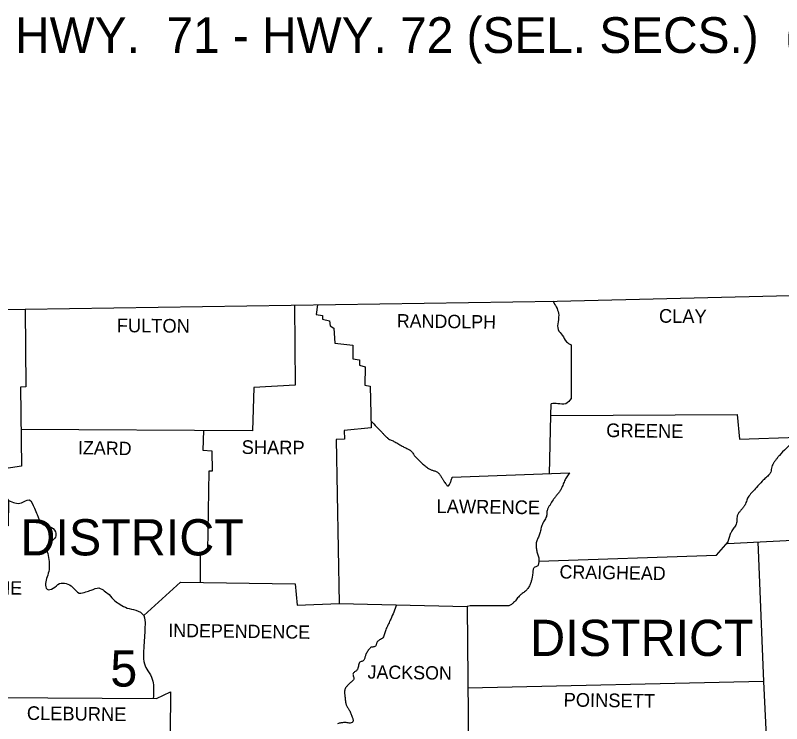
# Model space of a CAD drawing. Extents: x 6028647 to 6035072, y 5366486 to 5368495.
# Drawn here: x 6031371.9 to 6031613, y 5368223.1 to 5368446 of the extents above; entities that cross this region are included whole.
import ezdxf

# ---------------------------------------------------------------- set-up
doc = ezdxf.new("R2010")
doc.units = 0
doc.layers.add('Default', color=7, linetype='Continuous')
doc.layers.add('R_Border', color=7, linetype='Continuous')

msp = doc.modelspace()

# ---------------------------------------------------------------- linework, layer by layer
at = {"layer": 'Default'}
for p, q in [((6031540.38, 5368320.07), (6031540.46, 5368323.77)), ((6031595.96, 5368279.77), (6031597.04, 5368283.09))]:
    msp.add_line(p, q, dxfattribs=at)
for points in [[(6031071.37, 5368353.27), (6031233.07, 5368353.17), (6031374.96, 5368353.47), (6031542.36, 5368356.07), (6031619.96, 5368357.87)], [(6031459.66, 5368354.79), (6031459.86, 5368329.57), (6031446.86, 5368328.87), (6031446.46, 5368315.27), (6031373.63, 5368315.67)], [(6031466.94, 5368354.9), (6031466.56, 5368351.87), (6031468.56, 5368351.57), (6031468.46, 5368350.37), (6031470.76, 5368349.87), (6031470.96, 5368348.27), (6031472.06, 5368347.57), (6031472.36, 5368342.77), (6031478.06, 5368342.17), (6031478.06, 5368337.87), (6031480.16, 5368337.57), (6031480.16, 5368335.87), (6031481.96, 5368335.37), (6031481.86, 5368329.57), (6031483.46, 5368329.27), (6031483.86, 5368316.17), (6031475.36, 5368315.37), (6031475.46, 5368312.57), (6031472.86, 5368312.47), (6031473.76, 5368260.87), (6031514.06, 5368259.97), (6031514.76, 5368179.77), (6031488.46, 5368179.07), (6031487.94, 5368193.17)], [(6031374.96, 5368353.47), (6031375.16, 5368329.07), (6031373.46, 5368328.97), (6031373.76, 5368304.07), (6031366.76, 5368303.07), (6031367.36, 5368296.37), (6031369.76, 5368293.27), (6031369.56, 5368285.37), (6031355.97, 5368284.87), (6031355.46, 5368272.67), (6031343.07, 5368272.27), (6031342.47, 5368257.47), (6031343.16, 5368256.27), (6031343.47, 5368232.67), (6031364.86, 5368231.27), (6031364.56, 5368178.57), (6031381.56, 5368178.07), (6031381.56, 5368124.47), (6031368.16, 5368123.47), (6031367.16, 5368111.67), (6031344.67, 5368111.57)], [(6031546.76, 5368342.27), (6031546.76, 5368325.37)], [(6031539.94, 5368301.74), (6031540.38, 5368320.07), (6031540.46, 5368320.07), (6031598.96, 5368320.37), (6031599.76, 5368312.57), (6031618.12, 5368313.24)], [(6031431.08, 5368315.36), (6031430.86, 5368309.17), (6031433.66, 5368308.97), (6031433.76, 5368302.57), (6031432.76, 5368302.57), (6031432.36, 5368277.37), (6031430.06, 5368276.37), (6031430.06, 5368267.48)], [(6031509.36, 5368300.67), (6031546.23, 5368301.96)], [(6031595.96, 5368279.77), (6031671.86, 5368283.67)], [(6031536.62, 5368274.26), (6031592.46, 5368276.07), (6031596.14, 5368280.3)], [(6031605.54, 5368280.26), (6031607.26, 5368236.37), (6031609.3, 5368195.4)], [(6031412.26, 5368257.08), (6031423.86, 5368267.57), (6031459.86, 5368267.07), (6031460.56, 5368260.37), (6031473.76, 5368260.87)], [(6031527.16, 5368260.17), (6031514.96, 5368260.17), (6031514.06, 5368259.97)], [(6031607.26, 5368236.37), (6031514.29, 5368234.25)], [(6031364.86, 5368231.27), (6031416.26, 5368230.97), (6031420.66, 5368233.07), (6031420.36, 5368193.97), (6031417.36, 5368192.67), (6031414.66, 5368190.37), (6031413.76, 5368189.47), (6031413.66, 5368178.27), (6031374.76, 5368178.27)]]:
    msp.add_lwpolyline(points, dxfattribs=at)
for points in [[(6031619.96, 5368357.87), (6031620.05, 5368356.77), (6031620.17, 5368355.67), (6031620.3, 5368354.57), (6031620.46, 5368353.47), (6031620.7, 5368352.85), (6031621.1, 5368352.29), (6031621.54, 5368351.75), (6031621.86, 5368351.17), (6031621.99, 5368350.15), (6031621.87, 5368349.06), (6031621.79, 5368347.97), (6031621.86, 5368347.45), (6031622.06, 5368346.97), (6031622.82, 5368345.99), (6031623.76, 5368345.17), (6031624.48, 5368344.69), (6031625.22, 5368344.27), (6031625.96, 5368343.85), (6031626.66, 5368343.37), (6031628.11, 5368342.09), (6031628.72, 5368341.34), (6031629, 5368340.92), (6031629.26, 5368340.47), (6031629.63, 5368339.62), (6031629.84, 5368338.77), (6031629.91, 5368337.92), (6031629.86, 5368337.07), (6031629.69, 5368336.2), (6031629.44, 5368335.33), (6031629.21, 5368334.45), (6031629.06, 5368333.57), (6031629.01, 5368332.6), (6031628.98, 5368331.62), (6031628.94, 5368330.64), (6031628.86, 5368329.67), (6031628.46, 5368326.27), (6031628.28, 5368324.71), (6031628.12, 5368323.93), (6031628.01, 5368323.55), (6031627.86, 5368323.17), (6031626.82, 5368321.78), (6031625.46, 5368320.67), (6031624.89, 5368320.21), (6031624.31, 5368319.78), (6031623.73, 5368319.33), (6031623.16, 5368318.87), (6031621.06, 5368316.77), (6031620.67, 5368316.23), (6031620.33, 5368315.65), (6031619.99, 5368315.08), (6031619.56, 5368314.57), (6031616.96, 5368312.17), (6031614.36, 5368309.67), (6031612.26, 5368307.47), (6031611.69, 5368306.81), (6031611.16, 5368306.11), (6031610.65, 5368305.4), (6031610.16, 5368304.67), (6031609.86, 5368303.92), (6031609.71, 5368303.09), (6031609.54, 5368302.27), (6031609.39, 5368301.9), (6031609.16, 5368301.57), (6031608.61, 5368301), (6031608.02, 5368300.46), (6031607.43, 5368299.93), (6031606.86, 5368299.37), (6031605.06, 5368297.37), (6031602.66, 5368294.67), (6031602.27, 5368294.05), (6031602, 5368293.36), (6031601.76, 5368292.65), (6031601.46, 5368291.97), (6031600.93, 5368291.18), (6031600.3, 5368290.43), (6031599.68, 5368289.68), (6031599.16, 5368288.87), (6031598.95, 5368288.15), (6031598.89, 5368287.38), (6031598.84, 5368286.6), (6031598.66, 5368285.87), (6031598.34, 5368285.25), (6031597.94, 5368284.66), (6031597.53, 5368284.07), (6031597.16, 5368283.47), (6031597.04, 5368283.09)], [(6031540.95, 5368356.05), (6031542.76, 5368352.27), (6031542.66, 5368349.57), (6031542.66, 5368347.07), (6031543.96, 5368345.37), (6031545.26, 5368343.27), (6031546.76, 5368342.27)], [(6031546.76, 5368325.37), (6031545.06, 5368323.77), (6031542.56, 5368323.77), (6031540.46, 5368323.77)], [(6031483.8, 5368318.28), (6031485.47, 5368316.51), (6031487.16, 5368314.77), (6031487.4, 5368314.53), (6031488.09, 5368313.8), (6031488.56, 5368313.32), (6031488.81, 5368313.09), (6031488.94, 5368312.98), (6031489.06, 5368312.87), (6031489.58, 5368312.53), (6031490.14, 5368312.27), (6031490.71, 5368312.04), (6031491.26, 5368311.77), (6031492.57, 5368311.02), (6031493.86, 5368310.27), (6031494.44, 5368309.97), (6031495.03, 5368309.69), (6031495.89, 5368309.25), (6031496.03, 5368309.16), (6031496.16, 5368309.07), (6031496.61, 5368308.66), (6031496.96, 5368308.17), (6031497.29, 5368307.65), (6031497.47, 5368307.4), (6031497.66, 5368307.17), (6031498.7, 5368306.11), (6031499.76, 5368305.07), (6031500.27, 5368304.62), (6031500.79, 5368304.19), (6031501.33, 5368303.78), (6031501.86, 5368303.37), (6031502.68, 5368302.95), (6031503.59, 5368302.66), (6031504.46, 5368302.33), (6031504.84, 5368302.09), (6031505.01, 5368301.94), (6031505.16, 5368301.77), (6031505.46, 5368301.36), (6031505.73, 5368300.93), (6031505.99, 5368300.5), (6031506.26, 5368300.07), (6031506.45, 5368299.79), (6031506.64, 5368299.5), (6031507.02, 5368298.92), (6031507.39, 5368298.39), (6031507.58, 5368298.16), (6031507.67, 5368298.06), (6031507.72, 5368298.01), (6031507.76, 5368297.97), (6031507.88, 5368297.9), (6031507.99, 5368297.89), (6031508.21, 5368298.02), (6031508.65, 5368298.73), (6031509.04, 5368299.74), (6031509.21, 5368300.24), (6031509.36, 5368300.67)], [(6031546.23, 5368301.96), (6031545.39, 5368300.75), (6031544.66, 5368299.47), (6031544.35, 5368298.77), (6031544.09, 5368298.06), (6031543.81, 5368297.35), (6031543.46, 5368296.67), (6031542.9, 5368295.85), (6031542.29, 5368295.06), (6031541.66, 5368294.28), (6031541.06, 5368293.47), (6031540.1, 5368291.96), (6031539.66, 5368291.18), (6031539.26, 5368290.37), (6031539.13, 5368289.86), (6031539.1, 5368289.32), (6031539.07, 5368288.78), (6031538.96, 5368288.27), (6031538.64, 5368287.56), (6031538.25, 5368286.88), (6031537.87, 5368286.19), (6031537.56, 5368285.47), (6031537.35, 5368284.77), (6031537.16, 5368284.07), (6031536.97, 5368283.37), (6031536.76, 5368282.67), (6031536.55, 5368282.07), (6031536.31, 5368281.47), (6031536.07, 5368280.88), (6031535.86, 5368280.27), (6031535.75, 5368279.66), (6031535.74, 5368279.02), (6031535.79, 5368278.39), (6031535.86, 5368277.77), (6031536, 5368277.14), (6031536.2, 5368276.52), (6031536.41, 5368275.9), (6031536.56, 5368275.27), (6031536.63, 5368274.7), (6031536.61, 5368274.12), (6031536.52, 5368273.54), (6031536.45, 5368273.25), (6031536.36, 5368272.97), (6031536.06, 5368272.63), (6031535.6, 5368272.42), (6031535.14, 5368272.21), (6031534.86, 5368271.87), (6031534.79, 5368271.52), (6031534.73, 5368271.15), (6031534.66, 5368270.42), (6031534.59, 5368269.69), (6031534.46, 5368268.97), (6031534.2, 5368267.96), (6031533.86, 5368266.97), (6031533.31, 5368265.91), (6031532.96, 5368265.42), (6031532.56, 5368264.97), (6031532.11, 5368264.56), (6031531.62, 5368264.21), (6031531.12, 5368263.86), (6031530.66, 5368263.47), (6031530.15, 5368262.92), (6031529.68, 5368262.32), (6031529.19, 5368261.73), (6031528.66, 5368261.17), (6031527.96, 5368260.62), (6031527.58, 5368260.38), (6031527.16, 5368260.17)], [(6031369.76, 5368293.27), (6031373.76, 5368292.57), (6031376.16, 5368293.47), (6031377.86, 5368290.87), (6031378.76, 5368288.87), (6031380.26, 5368285.97), (6031382.66, 5368285.07), (6031384.46, 5368283.47), (6031384.46, 5368281.77), (6031382.86, 5368280.17), (6031381.66, 5368278.57), (6031382.06, 5368276.67), (6031382.46, 5368274.07), (6031382.46, 5368271.57), (6031381.86, 5368269.27), (6031381.36, 5368267.17), (6031381.86, 5368265.37), (6031383.76, 5368265.67), (6031385.76, 5368267.17), (6031387.86, 5368267.17), (6031389.86, 5368266.07), (6031391.96, 5368264.17), (6031394.06, 5368264.57), (6031395.76, 5368265.07), (6031398.16, 5368265.77), (6031399.86, 5368264.87), (6031401.36, 5368263.67), (6031403.16, 5368261.77), (6031404.86, 5368260.57), (6031407.06, 5368259.47), (6031409.76, 5368258.77), (6031412.26, 5368257.07), (6031412.66, 5368254.17), (6031412.56, 5368251.67), (6031412.36, 5368248.57), (6031412.16, 5368245.17), (6031412.46, 5368241.87), (6031413.56, 5368239.67), (6031414.96, 5368237.07), (6031415.36, 5368234.67), (6031415.26, 5368230.87)], [(6031491.83, 5368260.47), (6031490.94, 5368258.21), (6031489.96, 5368255.97), (6031489.62, 5368255.22), (6031489.27, 5368254.47), (6031488.91, 5368253.72), (6031488.56, 5368252.97), (6031488.32, 5368252.33), (6031488.12, 5368251.67), (6031487.91, 5368251.01), (6031487.66, 5368250.37), (6031487.29, 5368249.91), (6031486.77, 5368249.57), (6031486.22, 5368249.25), (6031485.97, 5368249.07), (6031485.76, 5368248.87), (6031485.59, 5368248.55), (6031485.48, 5368248.17), (6031485.36, 5368247.79), (6031485.16, 5368247.47), (6031484.79, 5368247.26), (6031484.31, 5368247.18), (6031483.84, 5368247.1), (6031483.46, 5368246.87), (6031483.27, 5368246.64), (6031483.09, 5368246.4), (6031482.75, 5368245.91), (6031482.44, 5368245.4), (6031482.16, 5368244.87), (6031481.99, 5368244.43), (6031481.87, 5368243.96), (6031481.75, 5368243.5), (6031481.56, 5368243.07), (6031481.28, 5368242.81), (6031480.88, 5368242.65), (6031480.47, 5368242.51), (6031480.16, 5368242.27), (6031480.03, 5368242.03), (6031479.93, 5368241.76), (6031479.8, 5368241.17), (6031479.67, 5368240.59), (6031479.53, 5368240.19), (6031479.46, 5368240.07), (6031479.18, 5368239.75), (6031478.81, 5368239.48), (6031478.44, 5368239.2), (6031478.16, 5368238.87), (6031478.11, 5368238.4), (6031478.26, 5368237.86), (6031478.38, 5368237.32), (6031478.26, 5368236.87), (6031478.18, 5368236.77), (6031478.1, 5368236.68), (6031477.52, 5368236.17), (6031477.13, 5368235.83), (6031476.76, 5368235.47), (6031476.42, 5368235.1), (6031476.09, 5368234.73), (6031475.79, 5368234.33), (6031475.66, 5368234.11), (6031475.56, 5368233.87), (6031475.44, 5368232.77), (6031475.56, 5368231.67), (6031475.64, 5368230.94), (6031475.72, 5368230.21), (6031475.85, 5368229.49), (6031475.95, 5368229.13), (6031476.06, 5368228.77), (6031476.28, 5368228.32), (6031476.54, 5368227.91), (6031476.82, 5368227.5), (6031477.06, 5368227.07), (6031477.55, 5368225.98), (6031477.77, 5368225.42), (6031477.96, 5368224.87), (6031478.08, 5368224.52), (6031478.14, 5368224.13), (6031478.09, 5368223.77), (6031478, 5368223.61), (6031477.94, 5368223.54), (6031477.86, 5368223.47), (6031477.25, 5368223.24), (6031476.62, 5368223.3), (6031475.99, 5368223.45), (6031475.67, 5368223.49), (6031475.36, 5368223.47), (6031474.84, 5368223.38), (6031474.31, 5368223.29), (6031473.79, 5368223.19), (6031473.26, 5368223.07)]]:
    msp.add_spline(points, degree=3, dxfattribs=at)

# ---------------------------------------------------------------- texts
for s, height, rotation, p in [('RANDOLPH', 4.201, 359.2583, (6031491.86, 5368347.77)), ('CLAY', 4.299, 359.2258, (6031574.36, 5368349.27)), ('FULTON', 4.3, 359.4996, (6031403.76, 5368346.27)), ('GREENE', 4.301, 359.2361, (6031557.76, 5368313.27)), ('IZARD', 4.199, 358.9258, (6031391.56, 5368307.87)), ('SHARP', 4.3, 359.3905, (6031443.06, 5368307.97)), ('LAWRENCE', 4.301, 359.2678, (6031504.36, 5368289.37)), ('CRAIGHEAD', 4.201, 359.1159, (6031543.06, 5368268.77)), ('STONE', 4.199, 359.4001, (6031354.66, 5368263.87)), ('INDEPENDENCE', 4.1993, 359.2187, (6031419.96, 5368250.37)), ('JACKSON', 4.199, 359.1352, (6031482.66, 5368237.27)), ('POINSETT', 4.3, 359.1987, (6031544.36, 5368228.47)), ('CLEBURNE', 4.3, 359.2535, (6031375.46, 5368224.27))]:
    msp.add_text(s, height=height, rotation=rotation, dxfattribs=at).set_placement(p)
for s, p in [('DISTRICT', (6031373.48, 5368276.02)), ('DISTRICT', (6031533.86, 5368244.37)), ('5', (6031401.75, 5368234.74))]:
    msp.add_text(s, height=11.4, dxfattribs=at).set_placement(p)
at = {"layer": 'R_Border'}
msp.add_text('HWY.  71 - HWY. 72 (SEL. SECS.)  (BENTON CO.) (S)', height=11.2447, dxfattribs=at).set_placement((6031371.79, 5368434.14))

doc.saveas('drawing.dxf')
